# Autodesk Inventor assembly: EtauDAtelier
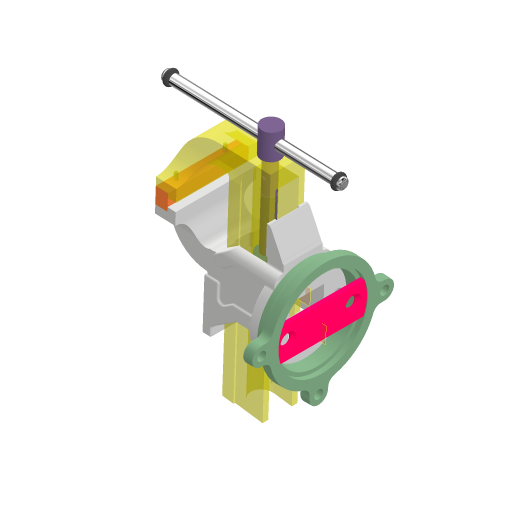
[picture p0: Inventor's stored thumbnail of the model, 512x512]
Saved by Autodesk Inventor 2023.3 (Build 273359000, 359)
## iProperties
Created: 2024-12
Part Number: EtauDAtelier
Document SubType Name: Assembly
Designer: Thier
Author: Thier
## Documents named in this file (5)
- E:\Dossier technique\Etau\01-Etau d'établi\TP04-Modification\EC02-TP05-02-Etau3D\EtauDAtelier.iam
- E:\Dossier technique\Etau\01-Etau d'établi\TP04-Modification\EC02-TP05-02-Etau3D\SEA\SEA-Socle.iam
- E:\Dossier technique\Etau\01-Etau d'établi\TP04-Modification\EC02-TP05-02-Etau3D\SEB\SEB-Mors.iam
- E:\Dossier technique\Etau\01-Etau d'établi\TP04-Modification\EC02-TP05-02-Etau3D\SEC\SEC-Poignée.iam
- E:\Dossier technique\Etau\01-Etau d'établi\TP04-Modification\EC02-TP05-02-Etau3D\SED\03-Vis de Manoeuvre.ipt
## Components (4 placed, 4 different names)
1. SEA-Socle:1 [sub-assembly] — Placage:1, Affleurement:1, Affleurement:2
2. SEB-Mors:1 [sub-assembly] — Placage:1, Affleurement:1, Affleurement:2, Logement:1
3. SEC-Poignée:1 [sub-assembly] — Placage:2
4. 03-Vis de Manoeuvre:1 — Logement:1, Placage:2
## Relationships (5: Mate 2, Flush 2, Insert 1)
- Placage:1 [Mate]: SEA-Socle:1 ↔ SEB-Mors:1
- Affleurement:1 [Flush]: SEA-Socle:1 ↔ SEB-Mors:1
- Affleurement:2 [Flush]: SEA-Socle:1 ↔ SEB-Mors:1
- Logement:1 [Insert]: SEB-Mors:1 ↔ 03-Vis de Manoeuvre:1
- Placage:2 [Mate]: SEC-Poignée:1 ↔ 03-Vis de Manoeuvre:1
